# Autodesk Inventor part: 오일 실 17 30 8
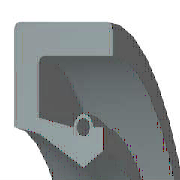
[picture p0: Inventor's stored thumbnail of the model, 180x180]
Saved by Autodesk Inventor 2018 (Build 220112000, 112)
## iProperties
IsCustomPart: 1
Created: 2012-02
Part Number: 오일 실 17 30 8
Material: 고무
Description: 오일-실
Document SubType Name: Modeling
Standard: KS B 2804
Designer: mduedu
Standards Organization: KS
Language: ko-KR
Size Designation: S - 17 30 8
Categories: <MemberInstance><Categories><Category DisplayName="샤프트 부품" InternalName="7f7aeb1f-a693-4053-b835-cee3144e0d98" Mnemonic="SHFT"><Category DisplayName="실링" Intern
Density: 0.93 g/cm^3
Appearance: 고무 - 검은색 - 버전 1.1
Author: mduedu
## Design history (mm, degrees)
revolve "본체" stored, may be unused: angle "d17" = 90 deg
revolve "스프링1" stored, may be unused: angle "d18" = 90 deg
body "Solid1"
sketch "스케치1"
  geometry: L1 (0, 15)-(8, 15); L2 (8, 15)-(8, 13.75); L3 (8, 13.75)-(1.75, 13.75); L4 (0, 15)-(0, 10.6); L5 (0, 10.6)-(1.75, 10.25); L6 (1.75, 10.25)-(4.9, 8.5); L7 (4.9, 8.5)-(0, 8.5); L8 (6.3, 9.375)-(6.3, 10.6); L9 (0, 0)-(9.586, 0) reference; L10 (4.9, 8.5)-(6.3, 9.375); L11 (0, 18)-(0, -3) reference; L12 (-1.917, 0)-(11.503, 0) reference; L13 (4.2, 10.6)-(1.75, 11.09); L14 (1.75, 11.09)-(1.75, 13.75); L15 (6.3, 10.6)-(5.6, 10.6); C1 r 0.455 at (4.9, 10.6); A1 r 0.7 centre (4.9, 10.6) between (5.6, 10.6) and (4.2, 10.6)
  constraints: 26 end point, 5 horizontal alignment, 4 perpendicular, 2 centre point, 2 collinear, 2 horizontal, 2 parallel, 2 point on circle, 2 point on line, 2 vertical alignment, 1 coincident
  dimensions: "d0" = 30 diameter of L1 L9 (= SD2); "d1" = 18.75 diameter of L8.start L9 (= ABDM); "d2" = 1.25 distance of L1.end L2.end (computed from SD); "d3" = 0.91 diameter of C1 (= SPDI); "d4" = 1.4 diameter of A1 (= SPDA); "d5" = 17 diameter of L6.end L9 (= NND); "d6" = 20.5 diameter of L5.end L9 (= TKDM); "d7" = 21.2 diameter of L4.end L9 (= HLDM); "d8" = 4.9 distance from line of C1.centre L4 (= SPDST); "d9" = 6.3 distance between parallel lines of L8 L4 (= SDI); "d10" = 8 distance between parallel lines of L2 L4 (= SWDT); "d12" = 1.75 distance between parallel lines of L14 L4 (= SD)
fillet "모깎기1" dims "d11" = 0.5 (= RR)
other parameters: "SD2" = 30 [user parameter; used in 1 equation term], "SWDT" = 8 [user parameter; used in 1 equation term], "RR" = 0.5 [user parameter; used in 1 equation term], "SD" = 1.75 [user parameter; used in 2 equation terms], "NND" = 17 [user parameter; used in 1 equation term], "SPDA" = 1.4 [user parameter; used in 1 equation term], "SPDI" = 0.91 [user parameter; used in 1 equation term], "TKDM" = 20.5 [user parameter; used in 1 equation term], "HLDM" = 21.2 [user parameter; used in 1 equation term], "ABDM" = 18.75 [user parameter; used in 1 equation term], "SDI" = 6.3 [user parameter; used in 1 equation term], "SPDST" = 4.9 [user parameter; used in 1 equation term], "d13" = 0, "d14" = 0, "d15" = 0, "LAB" = 0.35 [user parameter]
